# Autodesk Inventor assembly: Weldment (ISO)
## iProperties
Length Units: 11269
Angle Units: 11283
Time Units: 11279
Mass Units: 11290
Length Display Precision: 3
Angle Display Precision: 2
Part Number: Weldment (ISO)
Document SubType Name: Weldment
Created: 2002-06
Designer: smithga
Part Number: Ens_entretoise_moteur
Created: 2008-02
Designer: Pascal
Material: Aluminum soudé-6061
Control State: 0
Master: False
Shininess: 64.0
Angle Units: 11279
Time Units: 11290
Mass Units: 11283
Compacted: True
DESIGNATION: Entretoise motoréducteur
Density: 0.0
Volumn: 0.0
Area: 0.0
PropertySet Name: Model Information
Author: Pascal
